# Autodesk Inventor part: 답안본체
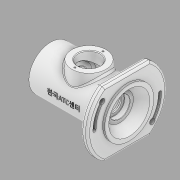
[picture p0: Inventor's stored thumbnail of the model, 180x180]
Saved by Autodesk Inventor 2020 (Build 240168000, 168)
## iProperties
Created: 2022-05
Part Number: 답안본체
Material: 알루미늄 6061
Document SubType Name: Modeling
Designer: Student
Density: 2.7 g/cm^3
Appearance: 알루미늄 - 평지
Mass: 683.489 g
Surface Area: 618.669 cm^2
Volume: 253.144 cm^3
Author: Student
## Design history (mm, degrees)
sketch "스케치1"
  geometry: L1 (-55.779, 0)-(55.779, 0); L2 (-51, 32)-(-51, 22.5); L3 (-51, 22.5)-(-43, 22.5); L4 (-43, 22.5)-(-43, 24); L5 (-43, 24)-(-40, 24); L6 (-40, 24)-(-40, 22.5); L7 (-40, 22.5)-(-29, 22.5); L8 (-29, 22.5)-(-29, 17.5); L9 (-29, 17.5)-(-26.75, 17.5); L10 (-26.75, 17.5)-(-26.75, 18.5); L11 (-26.75, 18.5)-(-25, 18.5); L12 (-25, 18.5)-(-25, 17.5); L13 (-25, 17.5)-(-14, 17.5); L14 (-14, 17.5)-(-14, 27); L15 (-14, 27)-(24, 27); L16 (24, 27)-(24, 17.5); L17 (24, 17.5)-(35, 17.5); L18 (35, 17.5)-(35, 15); L19 (35, 15)-(40, 15); L20 (40, 15)-(40, 11); L21 (40, 11)-(42, 11); L22 (42, 11)-(42, 15); L23 (42, 15)-(49.3, 15); L24 (64, 30)-(64, 36); L25 (64, 36)-(61, 36); L26 (61, 36)-(61, 58); L27 (61, 58)-(51, 58); L28 (51, 58)-(51, 32); L29 (51, 32)-(-51, 32); L30 (50, 20)-(64, 30); L31 (50, 20)-(50, 15.404); L32 (50, 15.404)-(49.3, 15); 3 further points
  constraints: 64 end point, 21 perpendicular, 7 point on line, 2 horizontal, 2 midpoint, 2 vertical, 1 coincident, 1 parallel, 1 vertical alignment
  dimensions: "d0" = 102 distance of L28.end L2.start; "d1" = 13 distance from line of L24.end L28; "d2" = 3 distance of L24.end L25.end; "d3" = 22 diameter of L21 L1; "d4" = 45 diameter of L3 L1; "d5" = 3 distance of L4.end L5.end; "d6" = 35 diameter of L13 L1; "d7" = 8 distance of L2.end L3.end; "d8" = 54 diameter of L15 L1; "d9" = 30 diameter of L23 L1; "d10" = 40 diameter of L30.start L1; "d11" = 60 diameter of L24.start L1; "d13" = 22 distance of L7.end L2.end; "d14" = 64 distance of L17.end L8.end; "d15" = 48 diameter of L5 L1; "d16" = 64 diameter of L29 L1; "d19" = 1.75 distance of L10.end L11.end; "d20" = 37 diameter of L11 L1; "d22" = 11 distance of L12.end L13.end; "d25" = 38 distance of L13.end L16.end; "d26" = 4 distance from line of L8.end L12; "d27" = 7.3 distance of L22.end L23.end; "d28" = 5 distance of L18.end L19.end; "d30" = 9.5 distance of L15.end L16.end; "d31" = 30 deg angle of L23 L32; "d32" = 0.7 horizontal distance of L31.end L23.end; "d33" = 14 distance between parallel lines of L24 L31; "d34" = 116 diameter of L27 L1; "d36" = 8.22142 distance from line of L1.end L24; "d37" = 72 diameter of L25 L1
revolve "회전1" sketch "스케치1" stored, may be unused: angle "d38" = 90 deg
sketch "스케치2"
  geometry: L1 (-33.985, 47)-(33.985, 47); L2 (-33.985, -47)-(33.985, -47); A1 r 58 centre (0, 0) between (-33.985, 47) and (33.985, 47) reference; A2 r 58 centre (0, 0) between (33.985, 47) and (-33.985, 47); A3 r 58 centre (0, 0) between (-33.985, -47) and (33.985, -47); 1 further point
  constraints: 9 point on circle, 4 end point, 2 centre point, 2 concentric, 2 horizontal
  dimensions: "d39" = 94 distance between parallel lines of L2 L1; "d40" = 47 distance from line of point (0, 0) L1
extrude "돌출1" cut sketch "스케치2" distance "d41" = 10; taper "d42" = 0 deg
sketch "스케치3"
  geometry: L1 (-68.074, 0)-(68.074, 0); L2 (-55.548, 46.61)-(55.548, -46.61); C1 r 15 at (0, 0) reference; A1 r 48 centre (0, 0) between (-48, 0) and (-34.115, -33.766); A2 r 48 centre (0, 0) between (-48, 0) and (-34.115, -33.766); A3 r 48 centre (0, 0) between (48, 0) and (36, 31.749); A4 r 48 centre (0, 0) between (-36.77, 30.854) and (-48, 0); A5 r 50.25 centre (0, 0) between (-38.494, 32.3) and (-50.25, 0); A6 r 45.75 centre (0, 0) between (-35.047, 29.408) and (-45.75, 0); A7 r 2.25 centre (-36.77, 30.854) between (-35.047, 29.408) and (-38.494, 32.3); A8 r 2.25 centre (-48, 0) between (-50.25, 0) and (-45.75, 0); A9 r 48 centre (0, 0) between (36.77, -30.854) and (48, 0); A10 r 50.25 centre (0, 0) between (38.494, -32.3) and (50.25, 0); A11 r 45.75 centre (0, 0) between (35.047, -29.408) and (45.75, 0); A12 r 2.25 centre (36.77, -30.854) between (35.047, -29.408) and (38.494, -32.3); A13 r 2.25 centre (48, 0) between (50.25, 0) and (45.75, 0); 4 further points
  constraints: 30 point on circle, 13 centre point, 10 tangent, 4 coincident, 4 concentric, 4 end point, 2 horizontal alignment, 2 midpoint, 2 point on line, 1 horizontal
  dimensions: "d43" = 96 diameter of A1; "d46" = 40 deg angle of L1 L2; "d47" = 2.25 radius of A7; "d48" = 2.25 radius of A12
extrude "돌출2" cut sketch "스케치3" distance "d49" = 10; taper "d50" = 0 deg
sketch "스케치4"
  geometry: A1 r 2.25 centre (48, 0) between (45.75, 0) and (50.25, 0) reference; A2 r 2.25 centre (36.77, 30.854) between (38.494, 32.3) and (35.047, 29.408) reference; A3 r 48 centre (0, 0) between (48, 0) and (36.77, 30.854); A4 r 52 centre (0, 0) between (52, 0) and (39.834, 33.425); A5 r 44 centre (0, 0) between (44, 0) and (33.706, 28.283); A6 r 4 centre (48, 0) between (44, 0) and (52, 0); A7 r 4 centre (36.77, 30.854) between (39.834, 33.425) and (33.706, 28.283); A8 r 2.25 centre (-48, 0) between (-45.75, 0) and (-50.25, 0) reference; A9 r 2.25 centre (-36.77, -30.854) between (-38.494, -32.3) and (-35.047, -29.408) reference; A10 r 48 centre (0, 0) between (-48, 0) and (-36.77, -30.854); A11 r 52 centre (0, 0) between (-52, 0) and (-39.834, -33.425); A12 r 44 centre (0, 0) between (-44, 0) and (-33.706, -28.283); A13 r 4 centre (-48, 0) between (-44, 0) and (-52, 0); A14 r 4 centre (-36.77, -30.854) between (-39.834, -33.425) and (-33.706, -28.283); 1 further point
  constraints: 20 point on circle, 10 centre point, 8 tangent
  dimensions: "d51" = 48 radius of A3; "d52" = 4 radius of A6; "d53" = 4 radius of A13; "d54" = 44 radius of A12
extrude "돌출3" cut sketch "스케치4" distance "d55" = 4.4; taper "d56" = 0 deg
sketch "스케치5"
  geometry: A1 r 2.25 centre (36.77, 30.854) between (38.494, 32.3) and (35.047, 29.408) reference; A2 r 4 centre (-36.77, -30.854) between (-39.834, -33.425) and (-33.706, -28.283) reference; 3 further points
  constraints: 2 coincident
hole "구멍1" sketch "스케치5" at (36.77, 30.854), (-36.77, -30.854) diameter "d57" = 8; stored, may be unused: countersink angle "d61" = 90 deg, drill point angle "d63" = 118 deg; dims "d58" = 4, "d59" = 4, "d60" = 2, "d62" = 6
node "작업 평면1"
sketch "스케치6"
  geometry: L1 (51, 32)-(51, -32) reference; C1 r 25 at (-5, 0); 1 further point
  constraints: 1 centre point, 1 horizontal alignment
  dimensions: "d66" = 25 radius of C1; "d67" = 56 distance from line of L1 C1.centre
extrude "돌출4" join sketch "스케치6" stored distance "d68" = 4.4; taper "d69" = 5 deg
sketch "스케치7"
  geometry: C1 r 16 at (0, 0); C2 r 25 at (0, 0) reference; 1 further point
  constraints: 1 centre point, 1 concentric
  dimensions: "d70" = 16 radius of C1
extrude "돌출5" cut sketch "스케치7" distance "d71" = 30; taper "d72" = 0 deg
sketch "스케치8"
  geometry: C1 r 16 at (0, 0) reference; A1 r 20.5 centre (0, 0) between (0, 20.5) and (0, -20.5); 1 further point
  constraints: 2 point on circle, 2 vertical alignment, 1 centre point, 1 coincident
  dimensions: "d73" = 41 diameter of A1
hole "구멍2" sketch "스케치8" at (0, 20.5), (0, -20.5) diameter "d74" = 2.459; stored, may be unused: countersink angle "d78" = 82 deg, drill point angle "d80" = 118 deg; dims "d75" = 6, "d76" = 3.023, "d77" = 2, "d79" = 8
fillet "모깎기1" dims "d81" = 0.6
fillet "모깎기2" dims "d82" = 0.5
fillet "모깎기3" dims "d83" = 3
chamfer "모따기1" distance "d84" = 1; stored, may be unused: second distance "d85" = 2, angle "d86" = 45 deg
node "작업 평면2"
sketch "스케치10"
  geometry: L1 (-16.105, -2.106)-(16.105, -2.106); L2 (16.105, -2.106)-(16.105, 2.106); L3 (16.105, 2.106)-(-16.105, 2.106); L4 (-16.105, 2.106)-(-16.105, -2.106); 2 further points
  constraints: 1 horizontal alignment, 1 midpoint, 2 other
feature "엠보싱1" sketch "스케치10" dims "d0" = 102, "d1" = 13, "d2" = 3, "d3" = 22, "d4" = 45, "d5" = 3, "d6" = 35, "d7" = 8, "d8" = 54, "d9" = 30, "d10" = 40, "d11" = 60, "d13" = 22, "d14" = 64, "d15" = 48, "d16" = 64, "d19" = 1.75, "d20" = 37, "d22" = 11, "d25" = 38, "d26" = 4, "d27" = 7.3, "d28" = 5, "d30" = 9.5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
node "솔리드1"
feature "A9D066F2-1C7D-4E18-AEED-F7BC21143FA4" dims "d57" = 8, "d58" = 4, "d59" = 4, "d60" = 2, "d61" = 90 deg, "d62" = 6, "d63" = 118 deg
other parameters: "d64" = 38
